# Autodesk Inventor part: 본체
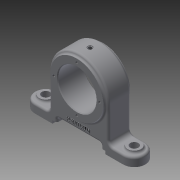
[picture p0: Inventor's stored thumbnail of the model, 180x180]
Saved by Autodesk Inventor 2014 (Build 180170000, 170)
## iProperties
Created: 2019-05
Part Number: 본체
Material: Generic
Document SubType Name: Modeling
Designer: kh
Density: 1 g/cm^3
Appearance: Default
Mass: 168.878 g
Surface Area: 318.859 cm^2
Volume: 168.878 cm^3
Author: kh
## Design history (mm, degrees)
sketch "Sketch5"
  geometry: L1 (-60, 0)-(60, 0); L2 (-60, -15)-(60, -15); L3 (60, 15)-(-60, 15); A1 r 15 centre (-60, 0) between (-60, 15) and (-60, -15); A2 r 15 centre (60, 0) between (60, -15) and (60, 15); 2 further points
  constraints: 8 end point, 4 point on circle, 4 tangent, 2 centre point, 1 coincident, 1 horizontal, 1 midpoint, 1 parallel
  dimensions: "d35" = 15 radius of A1; "d36" = 120 distance of L1.end L1.start
extrude "Extrusion5" new body sketch "Sketch5" distance "d37" = 12; taper "d38" = 0 deg
sketch "Sketch6"
  geometry: L1 (0, 0)-(0, 60); L2 (60, 12)-(-60, 12) reference; L3 (-40, 60)-(-40, 12); L4 (40, 60)-(40, 12); L5 (40, 12)-(-40, 12); A1 r 40 centre (0, 60) between (-40, 60) and (40, 60)
  constraints: 8 end point, 2 point on circle, 2 point on line, 2 tangent, 1 centre point, 1 coincident, 1 collinear, 1 parallel, 1 perpendicular, 1 vertical
  dimensions: "d39" = 60 distance of L1.start L1.end; "d40" = 80 diameter of A1
extrude "Extrusion6" join sketch "Sketch6" stored distance "d41" = 30; taper "d42" = 0 deg
sketch "Sketch7"
  geometry: C1 r 36 at (60, 60); A1 r 40 centre (60, 60) between (100, 60) and (20, 60) reference; 1 further point
  constraints: 1 centre point, 1 coincident
  dimensions: "d43" = 72 diameter of C1
extrude "Extrusion7" join sketch "Sketch7" distance "d44" = 3; taper "d45" = 0 deg
mirror "Mirror1"
hole "Hole2" diameter "d48" = 52; stored, may be unused: countersink angle "d52" = 90 deg, drill point angle "d54" = 118 deg; dims "d46" = 10, "d47" = 10, "d49" = 6, "d50" = 4, "d51" = 2, "d53" = 8
sketch "Sketch8"
  geometry: L1 (0, 0)-(120, 0) reference; L2 (24, 0)-(24, 4); L3 (24, 4)-(30, 4); L4 (30, 4)-(30, 10); L5 (30, 10)-(90, 10); L6 (90, 10)-(90, 4); L7 (90, 4)-(96, 4); L8 (96, 4)-(96, 0); L9 (24, 0)-(96, 0); 3 further points
  constraints: 16 end point, 4 perpendicular, 3 parallel, 2 equal length, 2 midpoint, 2 point on line, 1 collinear, 1 vertical alignment
  dimensions: "d55" = 60 distance of L4.end L5.end; "d56" = 72 distance between parallel lines of L2 L8; "d57" = 10 distance from line of L2.start L5; "d58" = 4 distance of L2.start L2.end
extrude "Extrusion8" cut sketch "Sketch8" stored distance "d59" = 3; taper "d60" = 0 deg
workplane "Work Plane1"
sketch "Sketch9"
  geometry: L1 (-40, -15)-(-40, 15) reference; L2 (-40, 15)-(-60, 15) reference; L3 (-60, -15)-(-40, -15) reference; C1 r 9 at (-60, 0); C2 r 9 at (60, 0); A1 r 15 centre (-60, 0) between (-60, 15) and (-60, -15) reference; A2 r 15 centre (60, 0) between (60, -15) and (60, 15) reference; 1 further point
  constraints: 2 centre point, 2 coincident
  dimensions: "d62" = 18 diameter of C1; "d63" = 18 diameter of C2
extrude "Extrusion9" join sketch "Sketch9" stored distance "d64" = 3; taper "d65" = 0 deg
sketch "Sketch10"
  geometry: C1 r 9 at (0, 0) reference; C2 r 9 at (120, 0) reference; 1 further point
hole "Hole3" sketch "Sketch10" at (0, 0), (120, 0) diameter "d66" = 11; stored, may be unused: countersink angle "d70" = 90 deg, drill point angle "d72" = 118 deg; dims "d67" = 6, "d68" = 4, "d69" = 2, "d71" = 8
sketch "Sketch11"
  geometry: L1 (0, 0)-(0, 31); C1 r 26 at (0, 0) reference; 2 further points
  constraints: 2 end point, 1 coincident, 1 vertical
  dimensions: "d73" = 31 distance of L1.start L1.end
hole "Hole4" sketch "Sketch11" at (0, 31) diameter "d74" = 3.242; stored, may be unused: countersink angle "d78" = 90 deg, drill point angle "d80" = 118 deg; dims "d75" = 6, "d76" = 4, "d77" = 2, "d79" = 8
pattern_circular "Circular Pattern1" dims angle "d82" = 360 deg
mirror "Mirror2"
workplane "Work Plane2"
sketch "Sketch12"
  geometry: 2 further points
  constraints: 1 coincident
hole "Hole5" sketch "Sketch12" at (0, 0) diameter "d85" = 5.134; stored, may be unused: countersink angle "d89" = 90 deg, drill point angle "d91" = 0 deg; dims "d86" = 8, "d87" = 7, "d88" = 1, "d90" = 10
sketch "Sketch13"
  geometry: 2 further points
  constraints: 1 coincident
hole "Hole6" sketch "Sketch13" at (0, 0) diameter "d92" = 2; stored, may be unused: countersink angle "d96" = 120 deg, drill point angle "d98" = 0 deg; dims "d93" = 9, "d94" = 5.13, "d95" = 1, "d97" = 10
sketch "Sketch14"
  geometry: 3 further points
  constraints: 2 vertical alignment, 1 other
hole "Hole7" sketch "Sketch14" at (0, 26) diameter "d99" = 3; stored, may be unused: countersink angle "d103" = 82 deg, drill point angle "d105" = 0 deg; dims "d100" = 9, "d101" = 6, "d102" = 1, "d104" = 10
fillet "Fillet1" dims "d106" = 6
chamfer "Chamfer1" distance "d107" = 1; stored, may be unused: second distance "d108" = 2, angle "d109" = 45 deg
fillet "Fillet3" dims "d111" = 3
fillet "Fillet4" dims "d112" = 3
fillet "Fillet5" dims "d113" = 3
fillet "Fillet6" dims "d114" = 3
fillet "Fillet7" dims "d115" = 3
sketch "Sketch15"
  geometry: L1 (43.408, 19.402)-(76.592, 19.402); L2 (76.592, 19.402)-(76.592, 14.598); L3 (76.592, 14.598)-(43.408, 14.598); L4 (43.408, 14.598)-(43.408, 19.402); L5 (43.408, 19.402)-(76.592, 14.598); L6 (33, 10)-(87, 10) reference; 2 further points
  constraints: 2 end point, 1 midpoint, 1 vertical alignment, 2 other
  dimensions: "d116" = 7 distance from line of L6 point (60, 17)
emboss "Emboss1" sketch "Sketch15" dims "d35" = 15, "d36" = 120, "d117" = 0.5, "d118" = 0
body "Solid2"
node "Projected Loop1"
other parameters: "d61" = 15
